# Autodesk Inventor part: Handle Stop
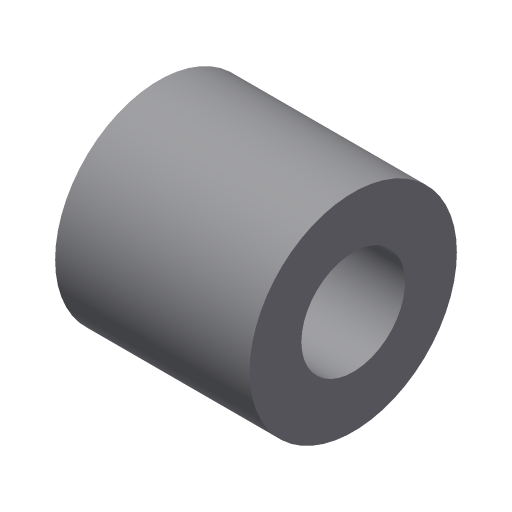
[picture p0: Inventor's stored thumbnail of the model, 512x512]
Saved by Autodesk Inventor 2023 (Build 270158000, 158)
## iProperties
Shininess: 77.0
Length Units: 11269
Angle Units: 11279
Time Units: 11290
Mass Units: 11283
Length Display Precision: 3
Angle Display Precision: 2
Compacted: True
Created: 2002-02
Part Number: Handle Stop
Document SubType Name: Modeling
Designer: ***
Density: 1 g/cm^3
Material: Generic
Mass: 2.36248 g
Surface Area: 14.8283 cm^2
Volume: 2.36248 cm^3
Appearance: Default
Density: 0.0
Volumn: 0.0
Area: 0.0
PropertySet Name: Model Information
Control State: 0
Master: False
Checked Out: False
Author: ***
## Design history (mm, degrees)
sketch "Sketch1"
  geometry: L1 (0, 0)-(0, -2); L2 (0, -2)-(8, -2); L3 (8, -2)-(8, 13); L4 (8, 13)-(4, 13); L5 (4, 13)-(4, 0); L6 (4, 0)-(0, 0)
  constraints: 12 end point, 4 parallel, 1 perpendicular, 1 vertical
  dimensions: "d0" = 16 diameter of L3 L1; "d1" = 8 diameter of L5 L1; "d2" = 2 distance of L1.start L1.end; "d3" = 15 distance of L2.end L3.end
revolve "Revolution1" sketch "Sketch1" stored, may be unused: angle "d4" = 90 deg
body "Solid1"
